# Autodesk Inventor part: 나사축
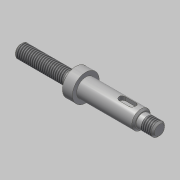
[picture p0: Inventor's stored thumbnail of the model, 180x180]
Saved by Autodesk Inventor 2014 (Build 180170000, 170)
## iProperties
Created: 2019-10
Part Number: 나사축
Material: 강철, 연강
Document SubType Name: Modeling
Designer: mduedu
Density: 1 g/cm^3
Appearance: Steel
Author: mduedu
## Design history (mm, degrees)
sketch "스케치1"
  geometry: L1 (0, 0)-(33, 0); L2 (33, 0)-(33, 4); L3 (33, 4)-(0, 4); L4 (0, 4)-(0, 0); L5 (33, 0)-(39, 0); L6 (39, 0)-(39, 8); L7 (39, 8)-(33, 8); L8 (33, 8)-(33, 0); L9 (39, 0)-(73, 0); L10 (73, 0)-(73, 5.5); L11 (73, 5.5)-(39, 5.5); L12 (39, 5.5)-(39, 0); L13 (73, 0)-(83, 0); L14 (83, 0)-(83, 4); L15 (83, 4)-(73, 4); L16 (73, 4)-(73, 0)
  constraints: 32 end point, 8 parallel, 4 horizontal, 4 perpendicular
  dimensions: "d0" = 83 distance between parallel lines of L14 L4; "d2" = 8 diameter of L15 L13; "d3" = 11 diameter of L11 L9; "d4" = 16 diameter of L7 L5; "d5" = 8 diameter of L3 L1; "d6" = 33 distance of L2.end L3.end; "d7" = 6 distance of L6.end L7.end; "d8" = 40 distance between parallel lines of L10 L8
revolve "회전1" sketch "스케치1" stored, may be unused: angle "d9" = 90 deg
sketch "스케치2"
  geometry: L1 (0, 4)-(0, -4) reference; L2 (0, -4)-(-33, -4) reference; L3 (-33, -4)-(-33, -8) reference; L4 (-33, -8)-(-39, -8) reference; L5 (-39, -8)-(-39, -5.5) reference; L6 (-39, -5.5)-(-73, -5.5) reference; L7 (-73, -5.5)-(-73, -4) reference; L8 (-73, -4)-(-83, -4) reference; L9 (-83, -4)-(-83, 4) reference; L10 (-83, 4)-(-73, 4) reference; L11 (-73, 4)-(-73, 5.5) reference; L12 (-73, 5.5)-(-39, 5.5) reference; L13 (-39, 5.5)-(-39, 8) reference; L14 (-39, 8)-(-33, 8) reference; L15 (-33, 8)-(-33, 4) reference; L16 (-33, 4)-(0, 4) reference; L17 (0, 0)-(-83, 0); L18 (-31, 3)-(-33, 3); L19 (-33, 3)-(-33, 4); L20 (-31, 3)-(-29.268, 4); L21 (-33, 4)-(-29.268, 4)
  constraints: 10 end point, 1 collinear, 1 midpoint, 1 point on line, 1 vertical
  dimensions: "d13" = 1 distance between parallel lines of L18 L21; "d15" = 30 deg angle of L16 L20; "d17" = 2 distance of L18.start L18.end
revolve "회전2" sketch "스케치2" stored, may be unused: angle "d12" = 90 deg
feature "스레드1" dims "d18" = 10, "d19" = 0
feature "스레드2" dims "d20" = 7, "d21" = 0
chamfer "모따기1" distance "d22" = 1; stored, may be unused: second distance "d23" = 2, angle "d24" = 30 deg
chamfer "모따기2" distance "d25" = 1; stored, may be unused: second distance "d26" = 2, angle "d27" = 30 deg
sketch "스케치3"
  geometry: L1 (-31, -3)-(-33, -3) reference; L2 (-33, -3)-(-33, -8) reference; L3 (-33, -8)-(-39, -8) reference; L4 (-39, -8)-(-39, -5.5) reference; L5 (-39, -5.5)-(-72, -5.5) reference; L6 (-72, -5.5)-(-73, -4.5) reference; L7 (-73, -4.5)-(-73, -4) reference; L8 (-73, -4)-(-82, -4) reference; L9 (-82, -4)-(-83, -3) reference; L10 (-83, -3)-(-83, 3) reference; L11 (-83, 3)-(-82, 4) reference; L12 (-82, 4)-(-73, 4) reference; L13 (-73, 4)-(-73, 4.5) reference; L14 (-73, 4.5)-(-72, 5.5) reference; L15 (-72, 5.5)-(-39, 5.5) reference; L16 (-39, 5.5)-(-39, 8) reference; L17 (-39, 8)-(-33, 8) reference; L18 (-33, 8)-(-33, 3) reference; L19 (-33, 3)-(-31, 3) reference; L20 (-31, 3)-(-29.268, 4) reference; L21 (-29.268, 4)-(-1, 4) reference; L22 (-1, 4)-(0, 3) reference; L23 (0, 3)-(0, -3) reference; L24 (0, -3)-(-1, -4) reference; L25 (-1, -4)-(-29.268, -4) reference; L26 (-29.268, -4)-(-31, -3) reference; L27 (-59, 5.5)-(-69, 5.5); L28 (-69, 5.5)-(-69, 3); L29 (-69, 3)-(-59, 3); L30 (-59, 3)-(-59, 5.5); 1 further point
  constraints: 8 end point, 2 parallel, 1 horizontal, 1 perpendicular, 1 point on line
  dimensions: "d28" = 20 distance between parallel lines of L30 L16; "d29" = 10 distance of L27.start L27.end; "d30" = 2.5 distance of L27.end L28.end
extrude "돌출1" cut sketch "스케치3" stored distance "d31" = 4; taper "d32" = 0 deg
fillet "모깎기1"
fillet "모깎기2"
node "솔리드1"
node "절단 모서리 투영1"
node "절단 모서리 투영2"
